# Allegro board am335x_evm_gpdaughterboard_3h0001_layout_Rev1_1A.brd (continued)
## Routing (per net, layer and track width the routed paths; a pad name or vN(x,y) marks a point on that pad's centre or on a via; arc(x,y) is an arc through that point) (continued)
N17609870: length 7.2
  TOP w0.121: v2(99.34,76.13) U43.C10 ; TP17.1 98.34,80.64 v1(99.41,79.57)
  LY6 w0.102: 99.2,78.65 99.2,78.55 98.94,78.29 98.94,76.94 99.34,76.54 v2(99.34,76.13)
  LY6 w0.121: v1(99.41,79.57) 99.41,79.14 99.2,78.93 99.2,78.65
N17609904: length 10.2
  TOP w0.121: TP18.1 98.34,83.03 98.8,82.56 v1(99.42,82.56) ; v2(100.34,76.13) U43.C11
  LY6 w0.102: v2(100.34,76.13) 100.34,76.21 100.74,76.61 100.74,77.39 100.62,77.51
  LY6 w0.121: v1(99.42,82.56) 100.01,82.56 100.62,81.95 100.62,77.51
N17609906: length 10.5
  TOP w0.121: v1(99.38,83.44) 99.95,83.44 TP19.1 ; v2(101.34,76.13) U43.C12
  LY6 w0.102: v2(101.34,76.13) 100.94,76.52 100.94,78.26 100.91,78.29 100.91,79.38
  LY6 w0.121: 100.91,79.38 100.91,83.16 100.62,83.44 v1(99.38,83.44)
N17609940: length 11.8
  TOP w0.121: v1(92.75,82.88) 93.37,82.88 93.99,82.26 93.99,81.93 TP21.1 ; v2(93.34,75.12) U43.D5
  LY3 w0.102: v2(93.34,75.12) 93.34,75.53 92.94,75.92 92.94,76.32 93.14,76.52 93.33,76.52 93.73,76.92 93.73,77.35 93.41,77.67 93.23,77.67 92.94,77.96 92.94,78.29 93.09,78.43 93.09,78.65
  LY3 w0.121: 93.09,78.65 93.09,78.99 92.56,79.52 92.56,82.68 v1(92.75,82.88)
N17609942: length 9.8
  TOP w0.121: v2(94.34,75.12) U43.D6 ; v1(94.59,82.69) 94.59,82.7 93.89,83.4 TP23.1
  LY3 w0.102: 94.59,78.65 94.59,78.43 94.73,78.29 94.73,75.94 94.34,75.54 v2(94.34,75.12)
  LY3 w0.121: v1(94.59,82.69) 94.59,78.65
N17609976: length 34.2
  TOP w0.121: TP24.1 96.4,83.7 95.29,83.7 93.7,85.29 85.57,85.29 v1(85.13,84.85) ; v2(95.34,75.12) U43.D7
  LY3 w0.102: v2(95.34,75.12) 94.74,74.53 94.74,73.91 94.4,73.57 94.14,73.57 93.73,73.15 93.73,72.93 93.53,72.73 92.13,72.73 91.73,73.13 91.73,73.33 91.33,73.73 89.17,73.73 89.03,73.88 88.81,73.88
  LY3 w0.121: v1(85.13,84.85) 85.13,82.16 88.01,79.28 88.01,74.19 88.33,73.88 88.81,73.88
N17609978: length 7.7
  TOP w0.121: v2(96.34,75.12) U43.D8 ; TP25.1 96.43,81.11 v1(96.58,80.96)
  LY3 w0.102: 96.58,78.65 96.58,78.43 96.73,78.29 96.73,75.94 96.34,75.54 v2(96.34,75.12)
  LY3 w0.121: v1(96.58,80.96) 96.58,78.65
N18557669: length 3.1
  TOP w0.102: 95.84,59.6 U43.V7
  TOP w0.121: TP54.1 94.91,58.54 95.84,59.47 95.84,59.6
N18557671: length 4.4
  TOP w0.102: U43.V2 89.95,59.74 89.95,59.6
  TOP w0.121: TP50.1 89.95,59.6
N18557677: length 3.1
  TOP w0.102: U43.V4 92.84,59.85 92.58,59.6
  TOP w0.121: TP51.1 91.73,58.75 92.58,59.6
N18557679: length 4.4
  TOP w0.102: U43.V5 93.84,59.73 93.71,59.6
  TOP w0.121: TP52.1 92.62,58.51 93.71,59.6
N18557681: length 3.3
  TOP w0.102: 94.58,59.6 94.84,59.85 U43.V6
  TOP w0.121: 94.58,59.6 93.38,58.4 TP53.1
N18557766: length 2.8
  TOP w0.102: U43.V8 96.84,59.6
  TOP w0.121: TP55.1 96.84,58.35 96.84,59.6
N18557786: length 5.3
  TOP w0.102: U43.U8 97.32,61.14 97.32,59.6
  TOP w0.121: 97.32,59.6 97.32,57.7 97.07,57.44 TP48.1
N18557788: length 4.5
  TOP w0.102: U43.U9 98.24,61.22 98.24,59.6
  TOP w0.121: TP49.1 98.84,58.49 98.24,59.09 98.24,59.6
N18559563: length 2
  TOP w0.102: U43.R1 88.81,63.63
  TOP w0.121: TP74.1 88.64,63.63 88.81,63.63
N18559577: length 9.1
  TOP w0.102: 88.81,66.33 89.52,65.63 U43.N1
  TOP w0.121: TP68.1 86.52,67.73 87.67,66.59 88.56,66.59 88.81,66.33
N18559591: length 2.6
  TOP w0.102: U43.P1 88.81,64.63
  TOP w0.121: TP72.1 87.36,64.63 88.81,64.63
N18559605: length 10.9
  TOP w0.102: 88.81,67.09 89.32,67.09 89.79,66.63 U43.M1
  TOP w0.121: 88.81,67.09 88.05,67.09 86.65,68.49 82.74,68.49 82.55,68.68 80.62,68.68 TP65.1
N18559619: length 2.5
  TOP w0.121: v2(90.33,63.13) U43.R2
  BOTTOM w0.102: v2(90.33,63.13) 89.8,63.66 89.8,63.69 TP75.1
N18559633: length 2.8
  TOP w0.121: v2(90.33,64.13) U43.P2
  BOTTOM w0.102: TP73.1 89.8,64.96 89.8,64.79 90.33,64.25 v2(90.33,64.13)
N18559722: length 3.6
  TOP w0.102: 88.81,65.06 90.21,65.06 90.77,65.63 U43.N2
  TOP w0.121: TP69.1 88.56,65.06 88.81,65.06
N18559724: length 14.4
  TOP w0.121: v2(91.33,65.13) U43.N3 ; TP70.1 v1(78.78,65.32)
  LY6 w0.102: v2(91.33,65.13) 88.81,65.13
  LY6 w0.121: v1(78.78,65.32) 81.19,65.32 81.44,65.57 83.98,65.57 84.43,65.13 88.81,65.13
N18559756: length 12.2
  TOP w0.121: U43.M2 90.33,66.13 89.52,66.13 88.81,66.84 87.92,66.84 86.65,68.11 82.77,68.11 82.46,68.42 81,68.42 TP66.1
N18559758: length 1.8
  TOP w0.121: v2(91.33,66.13) U43.M3
  BOTTOM w0.102: v2(91.33,66.13) 90.54,66.13 TP67.1
N18559789: length 2.6
  TOP w0.121: v2(91.33,67.13) U43.L3
  BOTTOM w0.102: TP64.1 90.3,67.13 v2(91.33,67.13)
N18559809: length 2.4
  TOP w0.121: v2(90.33,62.12) U43.T2
  BOTTOM w0.102: v2(90.33,62.12) 90.1,62.12 TP76.1
N18559823: length 2
  TOP w0.121: v2(91.33,64.13) U43.P3
  BOTTOM w0.102: TP34.1 90.46,65 v2(91.33,64.13)
N18560303: length 17.6
  TOP w0.102: 107.76,70.51 107.28,70.51 106.79,70.02 106.23,70.02 U43.J17
  TOP w0.121: 107.76,70.51 108.49,70.51 109.08,71.1 109.82,71.1 110.01,71.28 121.7,71.28 TP44.1
N18560305: length 16.5
  TOP w0.102: U43.J18 107.47,70.26 107.86,70.26
  TOP w0.121: 107.86,70.26 108.64,70.26 109.23,70.85 109.92,70.85 110.1,71.03 122.21,71.03 TP45.1
N18561900: length 17
  TOP w0.121: U43.J5 v2(93.34,70.13)
  LY6 w0.102: v2(93.34,70.13) 92.5,69.29 88.81,69.29
  LY6 w0.121: 88.81,69.29 79.12,69.29 v1(78.52,69.89)
  BOTTOM w0.121: TP57.1 v1(78.52,69.89)
N18561902: length 7.8
  TOP w0.121: U43.J4 v2(92.34,70.13)
  LY3 w0.102: v2(92.34,70.13) 91.66,69.45 88.81,69.45
  LY3 w0.121: 88.81,69.45 87.48,69.45 87.04,69.89 v1(86.64,69.89)
  BOTTOM w0.121: TP56.1 86.52,69.77 v1(86.64,69.89)
N18561972: length 3.2
  TOP w0.121: v2(92.34,66.13) U43.M4
  BOTTOM w0.102: v2(92.34,66.13) 92.32,66.13 91.79,66.65 91.79,67.41 TP77.1
N18561992: length 4.1
  TOP w0.121: v2(93.34,65.13) U43.N5
  BOTTOM w0.102: v2(93.34,65.13) 93.32,65.13 92.75,65.7 92.75,67.73 TP71.1
N18561994: length 12.5
  TOP w0.121: v2(92.34,65.13) U43.N4 ; TP43.1 v1(82.21,64.68)
  LY6 w0.102: 88.81,64.55 91.34,64.55 91.92,65.13 v2(92.34,65.13)
  LY6 w0.121: 88.81,64.55 88.62,64.55 88.17,64.1 82.79,64.1 v1(82.21,64.68)
N18562015: length 17.6
  TOP w0.121: v2(91.33,62.12) U43.T3 ; TP14.1 91.72,50.07 91.72,49.94 90.59,48.81 v1(90.59,48.68)
  LY3 w0.102: v2(91.33,62.12) 90.73,61.52 90.14,61.52 89.94,61.32 89.94,59.6
  LY3 w0.121: 89.94,59.6 89.94,58.46 89.45,57.96 89.45,49.82 v1(90.59,48.68)
N18562459: length 5.5
  TOP w0.102: U43.U7 95.93,61.62 96.3,61.25 96.3,59.6
  TOP w0.121: TP47.1 95.67,58.58 96.3,59.22 96.3,59.6
N18562461: length 5.6
  TOP w0.102: U43.U6 94.84,61.58 95.29,61.12 95.29,59.73 95.16,59.6
  TOP w0.121: 95.16,59.6 94.14,58.58 TP46.1
N18562540: length 22.9
  TOP w0.121: TP42.1 123.1,67.86 v1(122.47,67.22) ; v2(103.33,67.13) U43.L14
  LY6 w0.102: 107.86,66.72 104.18,66.72 103.78,67.13 v2(103.33,67.13)
  LY6 w0.121: v1(122.47,67.22) 122.21,66.97 122.21,66.59 121.91,66.28 120.36,66.28 119.54,67.09 118.91,67.09 118.02,66.2 116.62,66.2 116.24,66.59 108.24,66.59 108.1,66.72 107.86,66.72
N18562542: length 58.2
  TOP w0.121: v1(115.48,58.97) 117.39,57.06 117.39,53.63 119.8,51.22 122.47,51.22 126.94,55.7 126.94,70.36 TP27.1 ; v2(102.33,67.13) U43.L13
  BOTTOM w0.102: 106.21,59.6 106.12,59.69 104.03,59.69 103.73,59.99 103.73,60.29 103.5,60.52 103.2,60.52 102.73,60.99 102.73,61.29 102.5,61.52 102.2,61.52 101.73,61.99 101.73,62.29 101.5,62.52 101.2,62.52 100.94,62.78 100.94,66.35 101.15,66.56 101.77,66.56 v2(102.33,67.13)
  BOTTOM w0.121: v1(115.48,58.97) 114.85,58.33 107.48,58.33 106.21,59.6
N18562576: length 35.2
  TOP w0.121: TP28.1 v1(126.4,65.19) ; v2(101.34,66.13) U43.M12
  LY6 w0.121: v1(126.4,65.19) 125.77,64.55 121.7,64.55 121.69,64.56 119.55,64.56 119,64.01 119,61.67 116.81,59.47 115.1,59.47 v1(114.72,59.85)
  BOTTOM w0.102: 107.86,59.6 107.35,59.6 107.22,59.73 107.17,59.73 106.94,59.96 106.94,60.36 106.58,60.72 105.18,60.72 104.94,60.96 104.94,61.29 104.5,61.73 104.17,61.73 103.94,61.96 103.94,62.29 103.5,62.73 103.17,62.73 102.94,62.96 102.94,63.32 102.73,63.54 102.73,64.29 102.5,64.52 102.31,64.52 101.73,65.1 101.73,65.29 101.34,65.68 v2(101.34,66.13)
  BOTTOM w0.121: 107.86,59.6 112.69,59.6 112.94,59.85 v1(114.72,59.85)
N18562578: length 34.4
  TOP w0.121: TP29.1 v1(126.4,67.09) ; v2(102.33,66.13) U43.M13
  LY6 w0.121: v1(126.4,67.09) 125.26,67.09 123.86,65.7 119.67,65.7 118.53,64.55 118.53,61.76 116.88,60.11 v1(115.48,60.11)
  BOTTOM w0.102: 107.86,60.49 107.83,60.52 107.07,60.52 106.73,60.86 106.73,61.29 106.5,61.52 105.79,61.52 105.57,61.73 105.17,61.73 104.94,61.96 104.94,62.29 104.5,62.73 104.17,62.73 103.94,62.96 103.94,63.29 103.5,63.73 103.17,63.73 102.94,63.96 102.94,64.36 102.73,64.58 102.73,65.29 102.33,65.68 v2(102.33,66.13)
  BOTTOM w0.121: 107.86,60.49 115.1,60.49 v1(115.48,60.11)
N19691140: length 9.2
  TOP w0.121: U43.H6 v2(94.34,71.13)
  LY3 w0.102: 88.81,71.28 89.59,71.28 89.83,71.52 91.65,71.52 91.79,71.67 93.8,71.67 v2(94.34,71.13)
  LY3 w0.121: v1(87.41,71.28) 88.81,71.28
  BOTTOM w0.121: TP31.1 v1(87.41,71.28)
N19778977: length 2.7
  TOP w0.102: U43.F1 88.81,72.63
  TOP w0.121: TP35.1 87.6,72.63 88.81,72.63

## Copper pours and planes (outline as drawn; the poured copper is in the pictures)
AGND_AUD on LY3: 66.71,146.47 66.71,148.37 71.28,148.37 71.28,145.96 73.57,145.96 73.57,168.57 29.63,168.57 29.63,152.18 42.84,152.18 42.84,148.25 45.12,148.25 45.12,151.8 53.38,151.8 53.38,146.47
DGND on LY2_GND, LY7_GND: 1.27,1.27 168.73,1.27 168.73,168.73 1.27,168.73
V1_8D on LY5_PWR: 1.27,168.73 168.73,168.73 168.73,1.27 1.27,1.27
V3_3AUD on LY6: 60.11,152.06 60.87,152.82 66.33,152.82 66.59,153.07 66.59,156.76 57.06,156.76 57.06,152.06
V3_3D on TOP: 127.16,100.75 125.13,100.75 125.13,99.1 126.15,99.1 126.15,99.73 127.16,99.73
V3_3D on LY4_PWR: 1.27,168.73 168.73,168.73 168.73,1.27 1.27,1.27
V5_0D on LY4_PWR: 40.93,126.53 35.47,126.53 35.47,92.62 31.28,92.62 31.28,45.5 62.39,45.5 62.39,31.41 92.37,31.41 92.37,36.23 66.97,36.23 66.97,48.68 36.99,48.68 36.99,88.05 40.93,88.05
VDDSHV1 on LY5_PWR: 67.22,65.44 67.22,63.41 36.36,63.41 36.36,65.19 33.31,65.19 33.31,56.17 9.18,56.17 9.18,59.35 12.74,59.35 12.74,63.16 16.17,63.16 16.17,60.11 21.37,60.11 21.37,75.09 31.53,75.09 31.53,82.71 40.55,82.71 40.55,95.54 18.33,95.54 18.33,94.78 9.05,94.78 9.05,101.26 67.22,101.26 67.22,111.42 80.68,111.42 80.68,141.77 83.48,141.77 83.48,148.12 87.92,148.12 87.92,143.17 90.59,143.17 90.59,141.13 93.26,141.13 93.26,145.83 91.6,145.83 91.6,148.37 97.07,148.37 97.07,133.01 90.97,133.01 90.97,87.54 56.93,87.54 56.93,73.95 59.09,73.95 59.09,65.44
VDDSHV2 on LY5_PWR: 105.45,123.86 105.45,155.61 60.24,155.61 60.24,145.83 54.39,145.83 54.39,155.61 42.96,155.61 42.96,137.71 35.34,137.71 35.34,123.35 30.77,123.35 30.77,137.71 1.31,137.71 1.31,70.4 17.82,70.4 17.82,93 6.64,93 6.64,101.76 66.97,101.76 66.97,111.67 80.43,111.67 80.43,142.28 83.22,142.28 83.22,148.5 88.18,148.5 88.18,143.55 90.84,143.55 90.84,141.52 93,141.52 93,145.58 91.22,145.58 91.22,148.75 97.45,148.75 97.45,132.75 91.22,132.75 91.22,123.86
VDDSHV3 on TOP: 127.93,96.94 130.97,96.94 131.1,97.07 131.1,103.8 130.59,104.3 127.93,104.3 ; 3 cut-outs
VDDSHV3 on LY5_PWR: 110.02,110.4 110.02,100.88 129.2,100.88 129.2,110.4
VDDSHV6 on LY5_PWR: 123.61,97.95 123.61,86.52 95.41,86.52 95.41,82.08 68.49,82.08 68.49,74.21 57.19,74.21 57.19,87.03 91.6,87.03 91.6,89.95 108.5,89.95 108.5,97.95
Net_10 on LY6: 70.01,17.31 59.98,17.31 59.98,5.63 70.01,5.63
VCPLD_INT on LY4_PWR: 94.53,65.32 99.61,65.32 99.61,67.22 100.24,67.86 112.31,67.86 112.31,74.21 100.24,74.21 94.53,68.49

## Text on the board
BOTTOM: LAYER 8 - SECONDARY SIDE | 8 | PN# 3H0001
Ref Des/Silkscreen Bottom: 19 | 1 | 2 | 20 | SDMMC1
User.Comments: sdf | Green indicates power/gnd routing
TOP: LAYER 1 - PRIMARY SIDE | 1
Ref Des/Silkscreen Top: 2 | 20 | 19 | 5 | 1 | HEADPHONE OUT | 27 | 28 | 3 | LINE IN | 40 | 39 | SELECTION | PROFILE | GND | ARM MPU | AM335x GP DAUGHTERBOARD | REV 1.1A | Assm PN#: 4P0013 | SN#:_________________
LY2_GND: LAYER 2 - GND PLANE | 2
LY3: LAYER 3 - SIGNAL LAYER | 3
LY4_PWR: LAYER 4 - POWER PLANE | 4
LY5_PWR: LAYER 5 - POWER PLANE | 5
LY6: LAYER 6 - SIGNAL LAYER | 6
LY7_GND: LAYER 7 - GND PLANE | 7
DIMENSION: (OZ) | DRILL DRAWING | 15 | PROCESS NOTES: | 2. APPLY LPI SOLDERMASK OVER BARE COPPER (SMOBC), | COLOR: GREEN. SOLDERMASK SHALL | CONFORM TO IPC-SM-840, CLASS H. CURRENT REV. | 3. SOLDERMASK ARTWORK HAS ZERO (0) OVERSIZED PADS. | FABRICATION VENDOR IS ALLOWED TO ADJUST THE COMPONENT | SOLDERMASK PADS TO MEET THEIR TOOLING REQUIREMENTS. | 4. APPLY LPI SILKSCREEN OR EQUIVALENT PER THE ARTWORK. | COLOR: WHITE. | 1. PLATE ALL EXPOSED AREAS WITH ELECTROLESS | IMMERSION GOLD, NICKEL 150 MICROINCHES THK MIN | GOLD 5-15 MICROINCHES THK MIN. | 10. PLATED THROUGH SLOT INDICATED WITH MULTIPLE DRILL HITS SHOULD BE | 11. ALL VIAS TO HAVE SOLDERMASK. | FAB NOTES: | 1. ALL DIMENSIONS ARE IN INCHES, UNLESS | OTHERWISE NOTED. | 2. THE PWB SHALL BE FABRICATED TO IPC-6012, | CLASS 2 AND WORKMANSHIP SHALL CONFORM TO | IPC-A-600, CLASS 2. CURRENT REVISIONS. | 3. BOARD MATERIAL SHALL BE 180 Tg/350 Td ISOLA FR-370HR | OR EQUIVALENT, RoHS COMPLIANT AND LEAD FREE | ASSEMBLY CAPABLE.  BOARD MATERIAL SHALL | MEET OR EXCEED IPC-4101B. COLOR: NATURAL. | 4. BOARD MATERIAL & CONSTRUCTION TO BE U.L. | APPROVED AND MARKED ON THE FINISHED BOARD. | 5. MINIMUM COPPER WALL THICKNESS OF PLATED-THRU | HOLES TO BE .001 INCH, WITH A MINIMUM | ANNULAR RING OF .002 INCH. | 6. OVERALL BOARD THICKNESS TO BE .062 +/- 10% | AND APPLIES AFTER ALL LAMINATION AND PLATING | PROCESSES, MEASURED FROM COPPER TO COPPER. | 7. MAX. WARP & TWIST TO BE .0075 INCHES PER INCH. | 8. BOARD MUST BE ELECTRICALLY TESTED USING | SUPPLIED IPC-D-356 NETLIST. | 9. VENDOR MAY ADJUST LINE WIDTHS TO HOLD IMPEDANCE REQUIREMENTS. | FINISHED AS SMOOTH WALL BY VEDOR. | LAYER 6 - SIGNAL | LAYER 7 - GROUND PLANE | LAYER 8 - SECONDARY SIDE - SIGNAL | LAYER 1 - PRIMARY SIDE - SIGNAL | LAYER 2 - GROUND PLANE | LAYER 3 - SIGNAL | LAYER 4 - POWER PLANE | LAYER 5 - POWER PLANE | LAYER# | COPPER WEIGHT | HALF+PLATING | 1 | 2 | IMPEDANCE CONTROL | +/- 10% | 50ohm SINGLE ENDED | TRACE WIDTH | 4.75 | TRACE WIDTH / SPACE | 75ohm SINGLE ENDED | 4.75/5.00 | 100ohm DIFFERENTIAL | 3.75/6.00 | 3/76/6.00 | LAYER STACK-UP - ALL DIMENSIONS IN INCHES
720-2152-002: J6 | J4 | J3 | J1
User.5: AM335x EVM GENERAL PURPOSE DAUGHTERBOARD | 3H0001 | TEXAS INSTRUMENTS | 1.1A | 10-11-11 | TI-5965-01 | 15
User.9: 6 | 4 | 9 | 1 | 3 | 7 | A | K | R122 | R123 | R124 | R125 | R126 | R127 | R128 | R129 | R132 | R131 | C142 | C143 | C151 | C154 | R292 | C160 | C138 | R168 | C149 | C215 | C157 | R304 | TP3 | TP4 | TP5 | TP6 | C64 | TP7 | C81 | R64 | TP11 | C42 | C44 | C122 | C124 | C110 | C109 | C121 | R57 | TP16 | C123 | C120 | TP2 | TP1 | C71 | C119 | C65 | C27 | FB10 | C66 | TP37 | TP32 | TP12 | TP14 | C180 | TP22 | C8 | R422 | R414 | R411 | R413 | R419 | R426 | C6 | R395 | TP50 | C193 | C207 | R406 | C196 | R70 | TP21 | R389 | R391 | R388 | R409 | R112 | R289 | R290 | R291 | R293 | R294 | C128 | D8 | R384 | R230 | R241 | R246 | R252 | R257 | R271 | C137 | R240 | R245 | R251 | R256 | R260 | R267 | R191 | R189 | R179 | R180 | R182 | R183 | C133 | C132 | R306 | R313 | R381 | R254 | R259 | R262 | R266 | R270 | R273 | R300 | R181 | R173 | R350 | R154 | C82 | R427 | R158 | TP33 | C86 | C85 | C88 | R319 | TP34 | R194 | R423 | C112 | R238 | R23 | R449 | R429 | R412 | R430 | R432 | R220 | R436 | R216 | R363 | R364 | R62 | R25 | R379 | R236 | R91 | R232 | R324 | R48 | R90 | R89 | R361 | R438 | R296 | R26 | R6 | C60 | R10 | R314 | R27 | R3 | R30 | C12 | C11 | C14 | C13 | R45 | R250 | R28 | R29 | R249 | C140 | R234 | TP38 | TP39 | TP40 | TP41 | C199 | R347 | R403 | R402 | R410 | FB15 | C59 | C58 | C57 | C56 | C41 | TP25 | C32 | C29 | C79 | C80 | R325 | R68 | R187 | R188 | R60 | C91 | R53 | R63 | R19 | C48 | R16 | R199 | R14 | R203 | R207 | C17 | R4 | R373 | R372 | R233 | C63 | R367 | R371 | R368 | R366 | R370 | R365 | R369 | C7 | R431 | R435 | R393 | C198 | C194 | R408 | C200 | C190 | C213 | C169 | C165 | C167 | C168 | C170 | C166 | C164 | R277 | R268 | FB13 | R265 | R176 | R437 | R152 | R439 | R243 | R150 | R440 | C214 | R148 | R441 | C176 | C178 | R149 | R442 | C5 | R7 | R8 | R444 | R297 | R185 | R175 | R155 | R153 | R186 | R349 | R447 | R374 | R434 | R192 | R51 | R52 | R415 | R450 | R164 | R425 | C103 | R156 | C107 | C111 | R380 | R448 | R200 | R172 | R376 | R328 | U5 | R421 | R317 | R320 | R362 | R218 | R355 | R357 | TP24 | C10 | C9 | R221 | R2 | U21 | R77 | R378 | R1 | R235 | R392 | C206 | C205 | C208 | C209 | C210 | L7 | U26 | R390 | C204 | TP31 | U20 | C78 | C72 | R104 | R105 | R106 | R107 | R108 | R109 | R110 | R111 | R130 | R310 | R309 | C129 | C127 | C145 | C150 | C146 | R178 | C158 | C67 | C77 | C76 | C102 | C101 | C70 | C55 | C16 | C125 | R54 | R65 | TP19 | C26 | R462 | R461 | C73 | R79 | R73 | C203 | R407 | R74 | R75 | R71 | C115 | C118 | C162 | C187 | R386 | R147 | R146 | R145 | R144 | R143 | R142 | R141 | R140 | R138 | R134 | R133 | R139 | R137 | R135 | R136 | R274 | R157 | R159 | R161 | R163 | R165 | R167 | R169 | R171 | R184 | C183 | R269 | R258 | R239 | R272 | R299 | C175 | J12 | R301 | C177 | R303 | R302 | C179 | R248 | R352 | C75 | R295 | R298 | C83 | C114 | R69 | R377 | R170 | R428 | R346 | R85 | R318 | R211 | C113 | R197 | R166 | R321 | R335 | R205 | R204 | R87 | R84 | R229 | R225 | R224 | R212 | R201 | R5 | R215 | R351 | R228 | R219 | R226 | R404 | C28 | R92 | R227 | R348 | FB16 | R93 | R95 | R86 | R94 | TP26 | C43 | C24 | C33 | C45 | C54 | C30 | C184 | C153 | C152 | C144 | R276 | R275 | C116 | C147 | C136 | R322 | TP8 | C50 | C49 | C98 | C104 | C108 | TP35 | TP36 | C51 | C134 | C1 | C69 | C68 | C135 | C201 | C163 | C161 | R113 | C130 | R326 | R288 | C131 | R308 | R382 | R287 | R307 | R286 | R285 | R284 | R59 | R283 | R58 | R282 | R281 | R280 | C159 | R279 | C182 | R278 | R312 | R311 | R305 | R55 | L5 | C139 | R193 | R264 | R196 | R151 | R242 | R198 | R261 | R202 | R263 | R206 | C4 | R209 | R214 | R446 | R253 | R247 | R217 | R162 | R195 | R433 | R190 | R424 | R18 | R223 | R418 | R174 | R17 | R417 | R451 | R375 | R21 | R20 | R416 | R160 | R24 | R452 | R22 | R237 | R231 | R13 | R213 | R61 | R12 | R11 | R88 | R443 | R445 | R354 | R15 | R210 | R255 | R336 | R356 | R222 | R244 | R208 | R78 | R177 | R56 | R9 | R76 | R315 | R316 | R323 | R396 | R420 | TP49 | R397 | R405 | TP48 | R398 | TP47 | R394 | R399 | TP46 | C197 | R400 | R401 | C192 | C191 | C211 | C212 | C171 | C173 | C117 | C35 | C34 | C47 | C25 | C246 | R114 | R115 | R116 | R117 | R118 | R119 | R120 | R121 | C243 | R453 | R454 | R455 | C242 | FB4 | FB3 | C240 | C238 | C237 | C46 | C236 | C20 | R38 | R39 | R40 | R31 | C248 | R345 | R344 | R343 | R342 | R341 | R340 | R339 | R338 | R327 | R337 | R329 | R330 | R331 | R332 | R333 | R334 | U22 | J10 | 19 | 20 | C61 | 2 | C62 | Y2 | J16 | C232 | C233 | R473 | R471 | L4 | R466 | C234 | L1 | J5 | R477 | 28 | 27 | J19 | J6 | D2 | 40 | 39 | 10 | J15 | U25 | FB17 | FB18 | C172 | C23 | C22 | C37 | C38 | C39 | C36 | C53 | C52 | C40 | C247 | R385 | R387 | R383 | R472 | R37 | R34 | C241 | C251 | R464 | R35 | C252 | C254 | C249 | SW4 | SW3 | U24 | FB12 | C244 | FB11 | J7 | J8 | R32 | C18 | R49 | R470 | U6 | R469 | R468 | C2 | F1 | Y1 | U1 | D1 | J9 | U3 | J2 | Y3 | R359 | SW2 | SW5 | U11 | D3 | D4 | D5 | D6 | D7 | R96 | R97 | R98 | R99 | R100 | R101 | R102 | R103 | C257 | R33 | C235 | FB2 | FB1 | FB9 | R353 | U10 | J14 | 5 | R467 | R465 | C19 | R463 | C84 | R476 | R474 | R475 | L3 | C21 | C255 | J13 | R360 | R72 | R46 | C245 | R42 | FB7 | FB6 | FB8 | FB5 | C31 | C250 | C253 | C239 | R44 | R47 | R81 | R82 | R83 | R80 | L6 | C258 | C259 | FB14 | J3 | J4 | R41 | R43 | BT1 | R36 | U4 | L2 | R50 | SW1 | C256 | C3 | U15 | U16 | U14 | U13 | 99 | R358 | J11 | 100 | J1 | U2 | U19 | U8 | J30 | J25 | J23 | TP28 | U7 | TP30 | TP29 | TP27 | J17 | J29 | J24 | J20 | J35 | * | U18 | J27 | J26 | Q2 | Q3 | Q4 | Q1 | J28 | J31 | J21 | J32 | J22 | J34 | J33 | U9 | U17 | U27 | TP13 | TP20 | TP44 | TP42 | TP43 | TP45 | TP23 | TP9 | TP10 | TP17 | TP15 | TP18 | U12 | U23 | - | +
User.19: FIGURE | SIZE | 10.0 | 26.0 | 30.0 | 40.0 | 43.0 | 60.0 | 63.0 | 67.0 | 120.0 | 59.0 | 250.0 | DRILL CHART: TOP to BOTTOM | ALL UNITS ARE IN MILS | TOLERANCE | +3.0/-10.0 | +3.0/-3.0 | PLATED | NON-PLATED | QTY | 1597 | 120 | 2 | 152 | 9 | 3 | 1 | 4 | 8 | 6
